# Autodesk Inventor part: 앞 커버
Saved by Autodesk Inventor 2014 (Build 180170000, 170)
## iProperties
Created: 2026-06
Part Number: 앞 커버
Material: 알루미늄 6061
Document SubType Name: Modeling
Designer: dg
Density: 2.71 g/cm^3
Appearance: 알루미늄 - 평지
Mass: 41.8823 g
Surface Area: 74.5415 cm^2
Volume: 15.4547 cm^3
Author: jhkim
Creation Date: 2026-05-29
Sending System: Autodesk Inventor 2027
Preprocessor: ST-DEVELOPER v20.1
Author: dg
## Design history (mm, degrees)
node "앞 커버1"
node "솔리드1"
node "기준1"
